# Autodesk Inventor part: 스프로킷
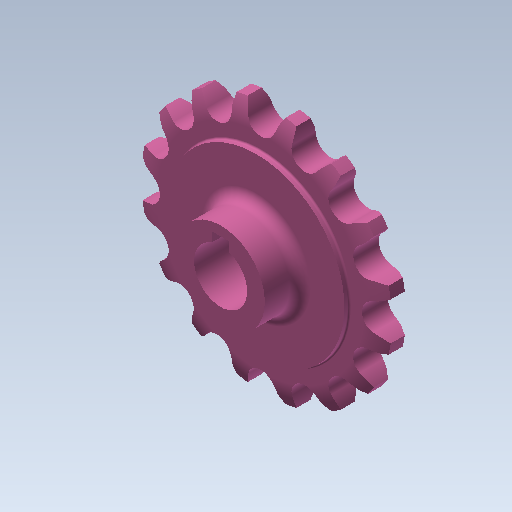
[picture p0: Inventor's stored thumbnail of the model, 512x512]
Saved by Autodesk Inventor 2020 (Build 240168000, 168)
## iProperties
Created: 2016-03
Part Number: 스프로킷
Material: 강철, 탄소
Document SubType Name: Modeling
Designer: mduedu
Density: 7.87 g/cm^3
Mass: 301.818 g
Surface Area: 124.882 cm^2
Volume: 38.3505 cm^3
Appearance: 분홍색
Author: mduedu
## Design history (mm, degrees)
sketch "스케치1"
  geometry: L1 (0, 5)-(25, 5); L2 (25, 5)-(25, 4.1); L3 (25.5, 3.6)-(29.125, 3.6); L4 (35.5, 2)-(35.5, 0); L5 (35.5, 0)-(0, 0); L6 (0, 0)-(0, 5); L7 (0, -5)-(25, -5); L8 (25, -5)-(25, -4.1); L9 (25.5, -3.6)-(29.125, -3.6); L10 (35.5, -2)-(35.5, 0); L11 (0, 0)-(0, -5); A1 r 13.5 centre (29.125, -9.9) between (35.5, 2) and (29.125, 3.6); A2 r 13.5 centre (29.125, 9.9) between (29.125, -3.6) and (35.5, -2); A3 r 0.5 centre (25.5, 4.1) between (25, 4.1) and (25.5, 3.6); A4 r 0.5 centre (25.5, -4.1) between (25.5, -3.6) and (25, -4.1); 2 further points
  constraints: 22 end point, 8 point on circle, 6 symmetric about line, 5 tangent, 4 centre point, 4 parallel, 4 point on line, 1 equal radius, 1 horizontal, 1 perpendicular, 1 other
  dimensions: "d0" = 71 diameter of L4 L6; "d2" = 50 diameter of L2 L6; "d3" = 1.6 vertical distance of L4.start L3.end; "d4" = 3.6 distance from line of L4.end L3; "d5" = 5 distance between parallel lines of L5 L1; "d6" = 13.5 radius of A1; "d15" = 0.5 radius of A3
revolve "회전1" sketch "스케치1" stored, may be unused: angle "d7" = 90 deg
sketch "스케치2" dims "d8" = 57.16, "d11" = 71
  geometry: L1 (0, 0)-(0, 28.58); A1 r 32.55 centre (0, 0) between (-16.114, 28.281) and (0, 32.55); A2 r 3.97 centre (0, 32.55) between (-3.838, 31.533) and (0, 28.58); A3 r 12.7 centre (-16.114, 28.281) between (-3.838, 31.533) and (-5.392, 35.088); A4 r 12.7 centre (16.114, 28.281) between (5.392, 35.088) and (3.838, 31.533); A5 r 3.97 centre (0, 32.55) between (0, 28.58) and (3.838, 31.533); A6 r 35.5 centre (0, 0) between (5.392, 35.088) and (-5.392, 35.088); 2 further points
  constraints: 12 point on circle, 6 centre point, 4 coincident, 3 symmetric about line, 2 end point, 1 point on line, 1 tangent, 1 vertical, 1 vertical alignment, 7 other
  dimensions: "d10" = 65.1 diameter of A1; "d12" = 12.7 radius of A3
extrude "돌출1" cut sketch "스케치2" extent not by distance; stored distance "d13" = 10; taper "d14" = 0 deg
sketch "스케치3"
  geometry: C1 r 12.5 at (0, 0); 1 further point
  constraints: 1 centre point, 1 coincident
  dimensions: "d19" = 25 diameter of C1
extrude "돌출2" join sketch "스케치3" distance "d20" = 10; taper "d21" = 0 deg
fillet "모깎기1" dims "d22" = 3
sketch "스케치4"
  geometry: L1 (-2.5, 0)-(2.5, 0); L2 (2.5, 0)-(2.5, 9.8); L3 (2.5, 9.8)-(-2.5, 9.8); L4 (-2.5, 9.8)-(-2.5, 0); C1 r 7.5 at (0, 0); 2 further points
  constraints: 8 end point, 2 coincident, 2 parallel, 1 centre point, 1 horizontal, 1 midpoint, 1 perpendicular
  dimensions: "d23" = 15 diameter of C1; "d25" = 5 distance of L2.end L3.end; "d26" = 9.8 distance of L1.end L2.end
extrude "돌출3" cut sketch "스케치4" extent not by distance; stored distance "d27" = 8; taper "d28" = 0 deg
node "솔리드1"
pattern_circular "원형 패턴1" dims angle "d17" = 360 deg
